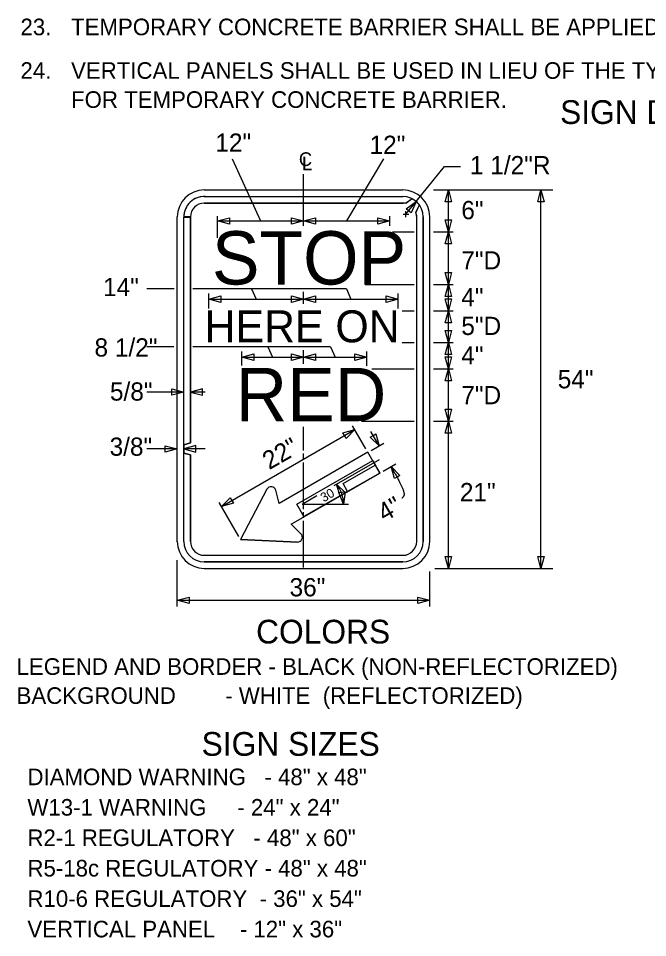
# Model space of a CAD drawing. Extents: x 16739 to 18486, y 7218 to 8208.
# Drawn here: x 17775.1 to 18093.1, y 7237.3 to 7702.3 of the extents above; entities that cross this region are included whole.
import ezdxf

# ---------------------------------------------------------------- set-up
doc = ezdxf.new("R2010")
doc.units = 0
for name, color, linetype in [('MT_SCRATCH_LEVEL_A', 7, 'Continuous'), ('TRAFFIC_SIGNS_PR', 7, 'Continuous'), ('TYPICAL_TEXT_DIMEN_EX', 7, 'Continuous'), ('TYPICAL_TEXT_DIMEN_PR', 7, 'Continuous')]:
    doc.layers.add(name, color=color, linetype=linetype)

msp = doc.modelspace()

# ---------------------------------------------------------------- linework, layer by layer
at = {"layer": 'MT_SCRATCH_LEVEL_A'}
for p, q in [((17919.21, 7597.41), (17919.21, 7623.46)), ((17919.21, 7557.96), (17919.21, 7563.96)), ((17919.21, 7527.6), (17919.21, 7534.53)), ((17919.21, 7483.63), (17919.21, 7495.76)), ((17919.21, 7479.19), (17919.21, 7482.15)), ((17919.21, 7454.07), (17919.21, 7477.72)), ((17919.21, 7449.64), (17919.21, 7452.59)), ((17919.21, 7424.52), (17919.21, 7448.16))]:
    msp.add_line(p, q, dxfattribs=at)
at = {"layer": 'TRAFFIC_SIGNS_PR'}
for p, q in [((17869.04, 7615.55), (17969.47, 7615.55)), ((17869.04, 7612.23), (17869.57, 7612.23)), ((17869.04, 7608.9), (17969.49, 7608.9)), ((17969.49, 7608.9), (17869.04, 7608.9)), ((17869.57, 7612.23), (17969.38, 7612.23)), ((17869.57, 7612.21), (17969.38, 7612.23)), ((17974.19, 7611.11), (17970.99, 7608.63)), ((17974.19, 7611.11), (17971.25, 7608.97)), ((17976, 7604.05), (17977.77, 7607.98)), ((17977.54, 7607.52), (17976, 7604.05)), ((17855.38, 7437.56), (17855.38, 7601.88)), ((17858.7, 7601.88), (17862.02, 7601.88)), ((17862.03, 7601.88), (17858.7, 7601.88)), ((17858.7, 7437.7), (17858.7, 7601.81)), ((17862.02, 7601.81), (17858.7, 7601.81)), ((17862.02, 7487.55), (17862.02, 7601.81)), ((17976.4, 7437.7), (17976.4, 7601.88)), ((17976.4, 7437.7), (17976.4, 7601.88)), ((17979.73, 7437.7), (17979.73, 7601.88)), ((17979.73, 7601.88), (17979.73, 7437.7)), ((17983.05, 7437.7), (17983.05, 7601.88)), ((17858.71, 7486.66), (17862.02, 7487.55)), ((17858.71, 7483.35), (17858.71, 7485.66)), ((17862.02, 7481.46), (17858.71, 7482.35)), ((17862.02, 7437.7), (17862.02, 7481.46)), ((17951.74, 7482.81), (17906.93, 7456.94)), ((17957.82, 7472.28), (17951.74, 7482.81)), ((17913.01, 7446.41), (17957.82, 7472.28)), ((17900.68, 7464.12), (17887.4, 7438.64)), ((17906.93, 7456.94), (17905.19, 7463.61)), ((17917.91, 7441.56), (17913.01, 7446.41)), ((17887.4, 7438.64), (17916.1, 7437.4)), ((17869.04, 7430.68), (17969.44, 7430.68)), ((17869.04, 7430.68), (17969.44, 7430.68)), ((17869.04, 7427.36), (17969.38, 7427.36)), ((17969.38, 7427.36), (17869.04, 7427.36)), ((17869.04, 7424.03), (17927.91, 7424.03)), ((17869.04, 7424.03), (17927.91, 7424.03)), ((17927.91, 7424.03), (17969.39, 7424.03))]:
    msp.add_line(p, q, dxfattribs=at)
msp.add_lwpolyline([(17858.7, 7437.7), (17858.7, 7601.81), (17862.02, 7601.81), (17862.02, 7487.55), (17858.71, 7486.66), (17858.71, 7482.35), (17862.02, 7481.46), (17862.02, 7437.7)], dxfattribs=at)
for points in [[(17957.82, 7472.28), (17919.44, 7450.29), (17915.82, 7456.61), (17954.2, 7478.6)], [(17957.82, 7472.28), (17941.48, 7462.92), (17939.16, 7466.98), (17955.5, 7476.33)]]:
    msp.add_lwpolyline(points, close=True, dxfattribs=at)
for centre, radius, start, end in [((17869.04, 7601.88), 13.67, 90, 180), ((17969.38, 7601.88), 13.67, 0, 90), ((17869.04, 7601.88), 10.34, 90, 180), ((17869.04, 7601.88), 10.34, 87.0749, 180), ((17869.04, 7601.88), 7.02, 90, 180), ((17869.04, 7601.88), 7.02, 90, 180), ((17969.38, 7601.88), 10.34, 0.0011, 90), ((17969.38, 7601.88), 10.34, 0, 90), ((17969.38, 7601.88), 7.02, 76.1968, 90), ((17969.6, 7605.14), 3.76, 68.3136, 91.7829), ((17962.34, 7593.94), 20.86, 42.2917, 55.3821), ((17969.38, 7601.88), 10.34, 42.6036, 55.6914), ((17972.18, 7602.22), 4.24, 355.4085, 25.5399), ((17969.38, 7601.88), 7.02, 0.0011, 18.4463), ((17902.83, 7462.99), 2.43, 14.678, 152.4708), ((17916.2, 7439.83), 2.43, 267.5292, 45.322), ((17869.04, 7437.7), 13.67, 180, 270), ((17869.04, 7437.7), 10.34, 180, 270), ((17869.04, 7437.7), 10.35, 180, 270), ((17869.04, 7437.7), 7.02, 180, 270), ((17869.04, 7437.7), 7.02, 180, 270), ((17969.38, 7437.7), 10.34, 270, 0), ((17969.38, 7437.7), 7.02, 270, 0), ((17969.38, 7437.7), 13.67, 270, 0), ((17969.38, 7437.7), 10.35, 270, 0), ((17969.38, 7437.7), 7.02, 270.4693, 0)]:
    msp.add_arc(centre, radius, start, end, dxfattribs=at)
at = {"layer": 'TYPICAL_TEXT_DIMEN_EX'}
for p, q in [((17900.68, 7464.12), (17887.4, 7438.64)), ((17906.93, 7456.94), (17905.19, 7463.61)), ((17913.01, 7446.41), (17917.92, 7441.56)), ((17916.1, 7437.4), (17887.4, 7438.64))]:
    msp.add_line(p, q, dxfattribs=at)
for centre, start, end in [((17902.83, 7462.99), 14.6782, 152.471), ((17916.2, 7439.83), 267.5295, 45.3222)]:
    msp.add_arc(centre, 2.43, start, end, dxfattribs=at)
at = {"layer": 'TYPICAL_TEXT_DIMEN_PR'}
for p, q in [((17883.12, 7631.29), (17897.44, 7599.85)), ((17959.68, 7631.29), (17940.99, 7599.85)), ((17976.14, 7609.71), (17990.42, 7627.41)), ((17990.42, 7627.41), (17998.51, 7627.41)), ((17984.97, 7615.55), (18045.29, 7615.55)), ((17990.79, 7609.48), (17992.42, 7615.55)), ((17992.42, 7594.27), (17992.42, 7615.55)), ((17992.42, 7615.55), (17994.04, 7609.48)), ((18037.57, 7609.48), (18039.19, 7615.55)), ((18039.19, 7424.03), (18039.19, 7615.55)), ((18039.19, 7615.55), (18040.82, 7609.48)), ((17970.98, 7603.31), (17976.14, 7609.71)), ((17971.07, 7606.01), (17976.14, 7609.71)), ((17976.14, 7609.71), (17973.6, 7603.97)), ((17992.42, 7609.48), (17990.79, 7609.48)), ((17994.04, 7609.48), (17992.42, 7609.48)), ((18039.19, 7609.48), (18037.57, 7609.48)), ((18040.82, 7609.48), (18039.19, 7609.48)), ((17970.98, 7601.84), (17970.98, 7604.79)), ((17972.33, 7604.99), (17971.07, 7606.01)), ((17973.6, 7603.97), (17972.33, 7604.99)), ((17875.66, 7591.25), (17875.66, 7602.33)), ((17875.66, 7599.85), (17881.72, 7601.47)), ((17875.66, 7599.85), (17919.21, 7599.85)), ((17881.72, 7598.22), (17875.66, 7599.85)), ((17881.72, 7601.47), (17881.72, 7599.85)), ((17881.72, 7599.85), (17881.72, 7598.22)), ((17913.15, 7599.85), (17913.15, 7601.47)), ((17913.15, 7601.47), (17919.21, 7599.85)), ((17919.21, 7599.85), (17913.15, 7598.22)), ((17913.15, 7598.22), (17913.15, 7599.85)), ((17919.21, 7599.85), (17925.28, 7601.47)), ((17919.21, 7599.85), (17962.77, 7599.85)), ((17925.28, 7598.22), (17919.21, 7599.85)), ((17925.28, 7601.47), (17925.28, 7599.85)), ((17925.28, 7599.85), (17925.28, 7598.22)), ((17956.7, 7599.85), (17956.7, 7601.47)), ((17956.7, 7601.47), (17962.77, 7599.85)), ((17956.7, 7599.85), (17956.7, 7601.47)), ((17956.7, 7601.47), (17962.77, 7599.85)), ((17962.77, 7599.85), (17956.7, 7598.22)), ((17956.7, 7598.22), (17956.7, 7599.85)), ((17962.77, 7599.85), (17956.7, 7598.22)), ((17956.7, 7598.22), (17956.7, 7599.85)), ((17962.77, 7597.41), (17962.77, 7602.33)), ((17969.5, 7603.31), (17972.46, 7603.31)), ((17992.42, 7594.27), (17990.79, 7600.34)), ((17990.79, 7600.34), (17992.42, 7600.34)), ((17992.42, 7600.34), (17994.04, 7600.34)), ((17994.04, 7600.34), (17992.42, 7594.27)), ((17964.11, 7594.27), (17975.12, 7594.27)), ((17984.97, 7594.27), (17994.9, 7594.27)), ((17990.79, 7588.2), (17992.42, 7594.27)), ((17992.42, 7567.67), (17992.42, 7594.27)), ((17992.42, 7594.27), (17994.04, 7588.2)), ((17992.42, 7588.2), (17990.79, 7588.2)), ((17994.04, 7588.2), (17992.42, 7588.2)), ((17992.42, 7567.67), (17990.79, 7573.74)), ((17990.79, 7573.74), (17992.42, 7573.74)), ((17992.42, 7573.74), (17994.04, 7573.74)), ((17994.04, 7573.74), (17992.42, 7567.67)), ((17950.37, 7567.67), (17975.12, 7567.67)), ((17984.97, 7567.67), (17994.9, 7567.67)), ((17990.79, 7561.6), (17992.42, 7567.67)), ((17992.42, 7554.37), (17992.42, 7567.67)), ((17992.42, 7567.67), (17994.04, 7561.6)), ((17853.79, 7565.43), (17839.99, 7565.43)), ((17940.93, 7565.43), (17863.31, 7565.43)), ((17871.33, 7555.48), (17871.33, 7563.15)), ((17892.91, 7565.43), (17895.27, 7560.29)), ((17940.93, 7565.43), (17943.15, 7560.29)), ((17967.09, 7555.48), (17967.09, 7563.15)), ((17871.33, 7560.29), (17877.4, 7561.91)), ((17871.33, 7560.29), (17919.21, 7560.29)), ((17877.4, 7558.66), (17871.33, 7560.29)), ((17877.4, 7561.91), (17877.4, 7560.29)), ((17877.4, 7560.29), (17877.4, 7558.66)), ((17913.15, 7560.29), (17913.15, 7561.91)), ((17913.15, 7561.91), (17919.21, 7560.29)), ((17919.21, 7560.29), (17913.15, 7558.66)), ((17913.15, 7558.66), (17913.15, 7560.29)), ((17919.21, 7560.29), (17925.28, 7561.91)), ((17919.21, 7560.29), (17967.09, 7560.29)), ((17925.28, 7558.66), (17919.21, 7560.29)), ((17925.28, 7561.91), (17925.28, 7560.29)), ((17925.28, 7560.29), (17925.28, 7558.66)), ((17961.03, 7560.29), (17961.03, 7561.91)), ((17961.03, 7561.91), (17967.09, 7560.29)), ((17967.09, 7560.29), (17961.03, 7558.66)), ((17961.03, 7558.66), (17961.03, 7560.29)), ((17992.42, 7561.6), (17990.79, 7561.6)), ((17992.42, 7554.37), (17990.79, 7560.44)), ((17990.79, 7560.44), (17992.42, 7560.44)), ((17994.04, 7561.6), (17992.42, 7561.6)), ((17992.42, 7560.44), (17994.04, 7560.44)), ((17994.04, 7560.44), (17992.42, 7554.37)), ((17969.1, 7554.37), (17975.12, 7554.37)), ((17984.97, 7554.37), (17994.9, 7554.37)), ((17990.79, 7548.3), (17992.42, 7554.37)), ((17992.42, 7538.41), (17992.42, 7554.37)), ((17992.42, 7554.37), (17994.04, 7548.3)), ((17992.42, 7548.3), (17990.79, 7548.3)), ((17992.42, 7538.41), (17990.79, 7544.48)), ((17990.79, 7544.48), (17992.42, 7544.48)), ((17994.04, 7548.3), (17992.42, 7548.3)), ((17992.42, 7544.48), (17994.04, 7544.48)), ((17994.04, 7544.48), (17992.42, 7538.41)), ((17853.62, 7536.15), (17839.99, 7536.15)), ((17932.92, 7536.15), (17863.31, 7536.15)), ((17901.2, 7536.15), (17903.59, 7530.95)), ((17932.92, 7536.15), (17935.17, 7530.95)), ((17969.1, 7538.41), (17975.12, 7538.41)), ((17984.97, 7538.41), (17994.9, 7538.41)), ((17990.79, 7532.34), (17992.42, 7538.41)), ((17992.42, 7525.11), (17992.42, 7538.41)), ((17992.42, 7538.41), (17994.04, 7532.34)), ((17887.96, 7526.71), (17887.96, 7533.81)), ((17887.96, 7530.95), (17894.03, 7532.58)), ((17887.96, 7530.95), (17919.21, 7530.95)), ((17894.03, 7529.32), (17887.96, 7530.95)), ((17894.03, 7532.58), (17894.03, 7530.95)), ((17894.03, 7530.95), (17894.03, 7529.32)), ((17913.15, 7530.95), (17913.15, 7532.58)), ((17913.15, 7532.58), (17919.21, 7530.95)), ((17919.21, 7530.95), (17913.15, 7529.32)), ((17913.15, 7529.32), (17913.15, 7530.95)), ((17919.21, 7530.95), (17925.28, 7532.58)), ((17919.21, 7530.95), (17951.13, 7530.95)), ((17925.28, 7529.32), (17919.21, 7530.95)), ((17925.28, 7532.58), (17925.28, 7530.95)), ((17925.28, 7530.95), (17925.28, 7529.32)), ((17945.07, 7530.95), (17945.07, 7532.58)), ((17945.07, 7532.58), (17951.13, 7530.95)), ((17951.13, 7530.95), (17945.07, 7529.32)), ((17945.07, 7529.32), (17945.07, 7530.95)), ((17951.13, 7526.5), (17951.13, 7533.81)), ((17992.42, 7532.34), (17990.79, 7532.34)), ((17992.42, 7525.11), (17990.79, 7531.18)), ((17990.79, 7531.18), (17992.42, 7531.18)), ((17994.04, 7532.34), (17992.42, 7532.34)), ((17992.42, 7531.18), (17994.04, 7531.18)), ((17994.04, 7531.18), (17992.42, 7525.11)), ((17953.73, 7525.11), (17975.12, 7525.11)), ((17984.97, 7525.11), (17994.9, 7525.11)), ((17990.79, 7519.04), (17992.42, 7525.11)), ((17992.42, 7498.51), (17992.42, 7525.11)), ((17992.42, 7525.11), (17994.04, 7519.04)), ((17992.42, 7519.04), (17990.79, 7519.04)), ((17994.04, 7519.04), (17992.42, 7519.04)), ((17858.71, 7513.25), (17839.99, 7513.25)), ((17852.64, 7513.25), (17852.64, 7514.88)), ((17852.64, 7514.88), (17858.71, 7513.25)), ((17858.71, 7513.25), (17852.64, 7511.63)), ((17852.64, 7511.63), (17852.64, 7513.25)), ((17868.09, 7514.88), (17862.02, 7513.25)), ((17862.02, 7513.25), (17868.09, 7511.63)), ((17869.5, 7513.25), (17862.02, 7513.25)), ((17868.09, 7513.25), (17868.09, 7514.88)), ((17868.09, 7511.63), (17868.09, 7513.25)), ((17992.42, 7498.51), (17990.79, 7504.58)), ((17990.79, 7504.58), (17992.42, 7504.58)), ((17992.42, 7504.58), (17994.04, 7504.58)), ((17994.04, 7504.58), (17992.42, 7498.51)), ((17948.47, 7498.51), (17975.12, 7498.51)), ((17984.97, 7498.51), (17994.9, 7498.51)), ((17990.79, 7492.44), (17992.42, 7498.51)), ((17992.42, 7424.03), (17992.42, 7498.51)), ((17992.42, 7498.51), (17994.04, 7492.44)), ((17877.74, 7455.36), (17945.13, 7494.26)), ((17939.06, 7492.64), (17945.13, 7494.26)), ((17939.87, 7491.23), (17939.06, 7492.64)), ((17945.13, 7494.26), (17940.69, 7489.82)), ((17950.72, 7484.57), (17943.99, 7496.22)), ((17957.41, 7486.09), (17953.25, 7493.29)), ((17940.69, 7489.82), (17939.87, 7491.23)), ((17952.97, 7490.53), (17954.38, 7491.34)), ((17957.41, 7486.09), (17952.97, 7490.53)), ((17954.38, 7491.34), (17955.79, 7492.15)), ((17955.79, 7492.15), (17957.41, 7486.09)), ((17992.42, 7492.44), (17990.79, 7492.44)), ((17994.04, 7492.44), (17992.42, 7492.44)), ((17855.38, 7484.51), (17839.99, 7484.51)), ((17849.31, 7484.51), (17849.31, 7486.14)), ((17849.31, 7486.14), (17855.38, 7484.51)), ((17855.38, 7484.51), (17849.31, 7482.89)), ((17849.31, 7482.89), (17849.31, 7484.51)), ((17864.78, 7486.19), (17858.71, 7484.56)), ((17858.71, 7484.56), (17864.78, 7482.93)), ((17869.5, 7484.56), (17858.71, 7484.56)), ((17864.78, 7484.56), (17864.78, 7486.19)), ((17864.78, 7482.93), (17864.78, 7484.56)), ((17953.42, 7483.78), (17959.81, 7487.47)), ((17934.74, 7465.98), (17957.62, 7479.19)), ((17959.5, 7473.25), (17965.89, 7476.94)), ((17965.58, 7471.94), (17963.49, 7475.55)), ((17965.12, 7469.49), (17963.49, 7475.55)), ((17963.49, 7475.55), (17967.94, 7471.11)), ((17966.53, 7470.3), (17965.12, 7469.49)), ((17967.94, 7471.11), (17966.53, 7470.3)), ((17937.7, 7460.62), (17935.89, 7466.64)), ((17935.89, 7466.64), (17940.46, 7462.33)), ((17918.54, 7456.62), (17925.9, 7460.87)), ((17937.1, 7462.49), (17938.72, 7462.65)), ((17939.33, 7456.62), (17937.1, 7462.49)), ((17939.08, 7461.48), (17937.7, 7460.62)), ((17938.72, 7462.65), (17940.33, 7462.82)), ((17940.46, 7462.33), (17939.08, 7461.48)), ((17940.33, 7462.82), (17939.33, 7456.62)), ((17886.53, 7440.15), (17876.61, 7457.32)), ((17877.74, 7455.36), (17882.19, 7459.8)), ((17883.81, 7456.98), (17877.74, 7455.36)), ((17882.19, 7459.8), (17883, 7458.39)), ((17883, 7458.39), (17883.81, 7456.98)), ((17918.54, 7456.62), (17941.98, 7456.62)), ((17855.38, 7404.85), (17855.38, 7428.18)), ((17992.42, 7424.03), (17990.79, 7430.1)), ((17990.79, 7430.1), (17992.42, 7430.1)), ((17992.42, 7430.1), (17994.04, 7430.1)), ((17994.04, 7430.1), (17992.42, 7424.03)), ((18039.19, 7424.03), (18037.57, 7430.1)), ((18037.57, 7430.1), (18039.19, 7430.1)), ((18039.19, 7430.1), (18040.82, 7430.1)), ((18040.82, 7430.1), (18039.19, 7424.03)), ((17985.5, 7424.03), (18045.29, 7424.03)), ((17983.05, 7404.85), (17983.05, 7422.51)), ((17855.38, 7407.93), (17861.44, 7409.55)), ((17861.44, 7409.55), (17861.44, 7407.93)), ((17976.99, 7407.93), (17976.99, 7409.55)), ((17976.99, 7409.55), (17983.05, 7407.93)), ((17855.38, 7407.93), (17983.05, 7407.93)), ((17861.44, 7406.3), (17855.38, 7407.93)), ((17861.44, 7407.93), (17861.44, 7406.3)), ((17983.05, 7407.93), (17976.99, 7406.3)), ((17976.99, 7406.3), (17976.99, 7407.93))]:
    msp.add_line(p, q, dxfattribs=at)
msp.add_arc((17924.98, 7457.28), 14.37, 357.3664, 40.6242, dxfattribs=at)
msp.add_open_spline([(17965.58, 7471.94), (17968.74, 7466.05), (17970.44, 7461.26), (17968.93, 7459.57), (17968.93, 7459.57)], degree=2, dxfattribs=at)

# ---------------------------------------------------------------- texts
at = {"layer": 'TYPICAL_TEXT_DIMEN_EX'}
for s, height, p in [('STOP', 26.972, (17872.89, 7567.69)), ('HERE ON', 16.181, (17869.2, 7538.44)), ('RED', 26.968, (17884.9, 7498.55))]:
    msp.add_text(s, height=height, dxfattribs=at).set_placement(p)
at = {"layer": 'TYPICAL_TEXT_DIMEN_PR'}
for s, height, p in [('23.', 8.4, (17776.14, 7693.82)), ('TEMPORARY CONCRETE BARRIER SHALL BE APPLIED AS PER THE CURRENT STANDARD PLAN.', 8.4, (17801.7, 7693.82)), ('24.', 8.4, (17776.13, 7671.77)), ('VERTICAL PANELS SHALL BE USED IN LIEU OF THE TYPE B HIGH INTENSITY LIGHT SHOWN IN THE STANDARD PLAN ', 8.4, (17801.7, 7671.77)), ('FOR TEMPORARY CONCRETE BARRIER.', 8.4, (17801.7, 7657.07)), ('SIGN DETAIL', 12, (18048.89, 7648.94)), ('12" ', 9.222, (17874.64, 7634.88)), ('12"', 9.222, (17952.58, 7633.76)), ('1 1/2"R', 9.222, (18003.31, 7623.47)), ('6"', 9.222, (17998.96, 7600.74)), ('7"D', 9.222, (17998.96, 7575.32)), ('14"', 9.222, (17817.88, 7561.8)), ('4"', 9.222, (17998.96, 7556.72)), ('5"D', 9.222, (17998.96, 7542.15)), ('8 1/2"', 9.222, (17813.56, 7531.25)), ('4"', 9.222, (17998.96, 7527.26)), ('54"', 9.222, (18047.7, 7515.17)), ('5/8"', 9.222, (17821.36, 7508.95)), ('7"D', 9.222, (17998.96, 7507.11)), ('3/8"', 9.222, (17821.18, 7481.05)), ('21"', 9.222, (17998.24, 7458.06)), ('36" ', 9.222, (17912.14, 7409.92)), ('COLORS', 12, (17895.23, 7386.06)), ('LEGEND AND BORDER - BLACK (NON-REFLECTORIZED)', 8.4, (17774.16, 7370.2)), ('BACKGROUND        - WHITE  (REFLECTORIZED)', 8.4, (17774.16, 7355.5)), ('SIGN SIZES', 12, (17867.69, 7329.25)), ('DIAMOND WARNING   - 48" x 48"', 8.4, (17779.65, 7314.37)), ('W13-1 WARNING     - 24" x 24"', 8.4, (17779.65, 7298.97)), ('R2-1 REGULATORY   - 48" x 60"', 8.4, (17779.65, 7283.57)), ('R5-18c REGULATORY - 48" x 48"', 8.4, (17779.65, 7268.17)), ('R10-6 REGULATORY  - 36" x 54"', 8.4, (17779.65, 7252.77)), ('VERTICAL PANEL    - 12" x 36"', 8.4, (17779.65, 7237.37))]:
    msp.add_text(s, height=height, dxfattribs=at).set_placement(p)
for s, height, rotation, p in [('C', 6.93, 0, (17916.85, 7627.66)), ('L', 6.93, 0, (17918.41, 7625.53)), ('22"', 9.222, 29.9375, (17901.88, 7473.74)), ('30', 4.618, 30, (17929.41, 7457.44)), ('4"', 9.222, 29.9998, (17960.07, 7447.4))]:
    msp.add_text(s, height=height, rotation=rotation, dxfattribs=at).set_placement(p)

doc.saveas('drawing.dxf')
